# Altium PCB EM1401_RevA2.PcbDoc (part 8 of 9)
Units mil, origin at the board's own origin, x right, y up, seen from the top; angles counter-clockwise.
Board outline 7800 x 5300 mil, 6 copper layers (Top Layer, MidLayer1, MidLayer2, MidLayer3, MidLayer4, Bottom Layer), stack 16.8 mil thick; 751 components, 531 nets, 2554 pads, 1388 vias.
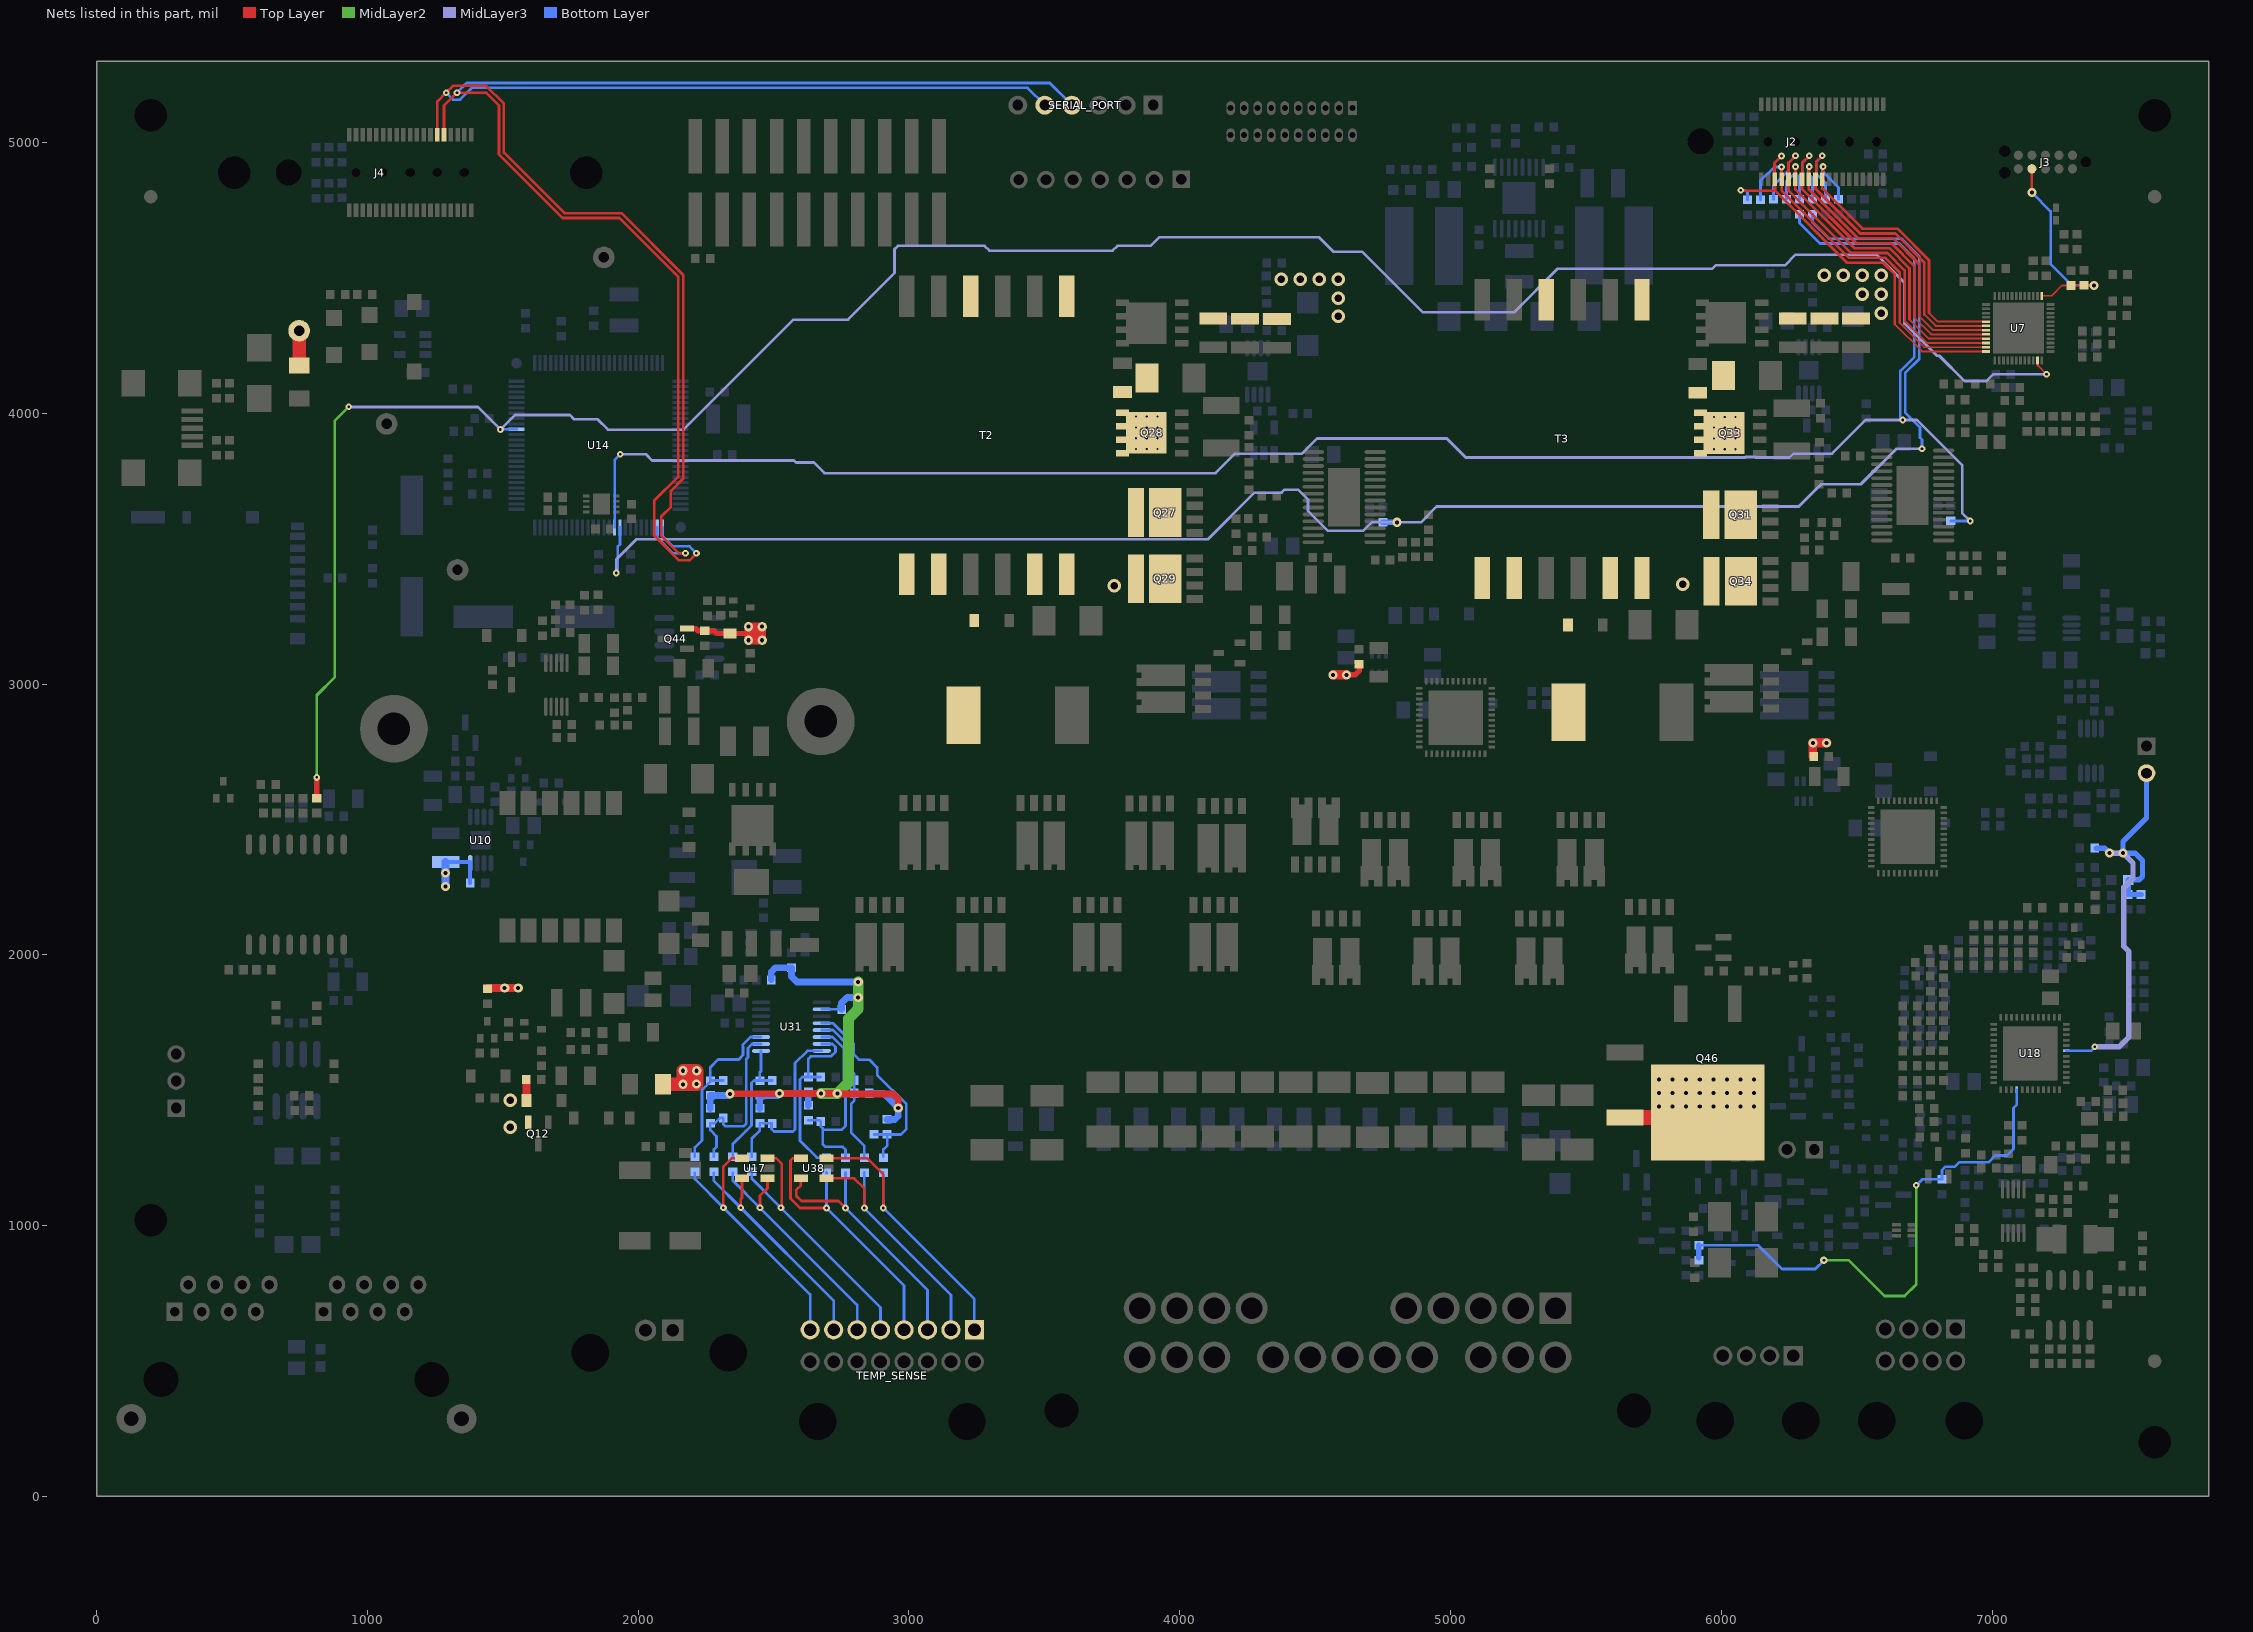
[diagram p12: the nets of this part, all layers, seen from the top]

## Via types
v1: diameter 25, hole 10, Top Layer to Bottom Layer, tented both sides, 275 vias
v2: diameter 16, hole 8, Top Layer to Bottom Layer, tented both sides, 240 vias
v3: diameter 34, hole 15, Top Layer to Bottom Layer, tented both sides, 158 vias
v4: diameter 34, hole 15, Top Layer to Bottom Layer, 154 vias
v5: diameter 34, hole 15, Top Layer to Bottom Layer, tented top, 95 vias
v6: diameter 34, hole 15, Top Layer to Bottom Layer, tented bottom, 89 vias
v7: diameter 25, hole 10, Top Layer to Bottom Layer, tented bottom, 75 vias
v8: diameter 25, hole 10, Top Layer to Bottom Layer, 62 vias
v9: diameter 28, hole 8, Top Layer to Bottom Layer, tented both sides, 60 vias
v10: diameter 24, hole 8, Top Layer to Bottom Layer, 53 vias
v11: diameter 25, hole 10, Top Layer to Bottom Layer, tented top, 28 vias
v12: diameter 50, hole 28, Top Layer to Bottom Layer, 28 vias
v13: diameter 25, hole 8, Top Layer to Bottom Layer, tented both sides, 18 vias
v14: diameter 50, hole 28, Top Layer to Bottom Layer, tented top, 12 vias
v15: diameter 25, hole 8, Top Layer to Bottom Layer, tented top, 9 vias
v16: diameter 20, hole 8, Top Layer to Bottom Layer, tented both sides, 9 vias
v17: diameter 24, hole 8, Top Layer to Bottom Layer, tented bottom, 4 vias
v18: diameter 24, hole 8, Top Layer to Bottom Layer, tented top, 4 vias
v19: diameter 28, hole 10, Top Layer to Bottom Layer, tented both sides, 3 vias
v20: diameter 35, hole 14, Top Layer to Bottom Layer, 3 vias
v21: diameter 50, hole 28, Top Layer to Bottom Layer, tented both sides, 2 vias
v22: diameter 50, hole 28, Top Layer to Bottom Layer, tented bottom, 2 vias
v23: diameter 30, hole 14, Top Layer to Bottom Layer, tented top, 2 vias
v24: diameter 28, hole 10, Top Layer to Bottom Layer, 1 vias
v25: diameter 35, hole 14, Top Layer to Bottom Layer, tented both sides, 1 vias
v26: diameter 35, hole 14, Top Layer to Bottom Layer, tented top, 1 vias

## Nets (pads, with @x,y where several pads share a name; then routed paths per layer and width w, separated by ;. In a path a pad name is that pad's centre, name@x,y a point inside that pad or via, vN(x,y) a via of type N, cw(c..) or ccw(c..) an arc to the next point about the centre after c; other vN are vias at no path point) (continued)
SP9: J2.19 R284.1 U7.41 | length 1149.5
  Top Layer w7: 6767,4371 6799.38,4338.62 U7.41@6977.91,4338.62
  Top Layer w10: v1(6376,4911) 6376,4867 J2.19@6373,4864 6373,4829.72 6520.72,4682 6650.35,4682 6767,4565.35 6767,4371
  Bottom Layer w10: v1@6373,4911 6373,4894 6433,4834 R284.1@6433,4791
SP10: J2.17 R282.1 U7.42 | length 1268.4
  Top Layer w7: 6749,4365 6791.13,4322.87 U7.42@6977.91,4322.87
  Top Layer w10: v1(6373,4951) 6350.5,4928.5 6350.5,4866.5 J2.17@6348,4864 6348,4829.27 6513.27,4664 6642.89,4664 6749,4557.89 6749,4365
  Bottom Layer w10: v1(6373,4951) 6350.5,4928.5 6350.5,4885.5 6385,4851 R282.1@6385,4791
SP11: J2.15 R281.1 U7.43 | length 1194.4
  Top Layer w7: 6731,4359 6782.87,4307.13 U7.43@6977.91,4307.13
  Top Layer w10: v1@6322,4911 v1@6323,4911 ; v1(6325,4911) 6325,4866 J2.15@6323,4864 6323,4828.81 6505.81,4646 6635.44,4646 6731,4550.44 6731,4359
  Bottom Layer w10: v1@6322,4911 6322,4883 6337,4868 R281.1@6337,4790
SP12: J2.13 R268.1 U7.44 | length 1324.4
  Top Layer w7: 6713,4353 6774.62,4291.38 U7.44@6977.91,4291.38
  Top Layer w10: J2.13@6298,4864 J2.13@6299,4865 ; v1(6325,4951) 6299.5,4925.5 6299.5,4865.5 J2.13@6299,4865 ; 6713,4353 6713,4542.98 6627.98,4628 6498.35,4628 6298,4828.35 6298.97,4863.97 J2.13@6299,4865
  Bottom Layer w10: R268.1@6289,4790 6289,4877 6299.5,4887.5 6299.5,4925.5 v1(6325,4951)
SP13: J2.11 R267.1 U7.45 | length 1264.3
  Top Layer w7: 6695,4347 6766.37,4275.63 U7.45@6977.91,4275.63
  Top Layer w10: v1@6271,4911 v1@6273,4911 ; v1(6274,4911) 6274,4865 J2.11@6273,4864 6273,4827.9 6490.9,4610 6620.52,4610 6695,4535.52 6695,4347
  Bottom Layer w10: R267.1@6241,4790 6241,4857 6274,4890 v1(6274,4911)
SP14: J2.9 R258.1 U7.46 | length 1406.1
  Top Layer w7: 6677,4341 6758.12,4259.88 U7.46@6977.91,4259.88
  Top Layer w10: v1(6274,4951) 6248,4925 J2.9@6248,4864 6248,4823 6479,4592 6613.07,4592 6677,4528.07 6677,4341
  Bottom Layer w10: R258.1@6193,4790 6193,4841 6248,4896 6248,4925 v1(6274,4951)
SP15: J2.7 R254.1 U7.47 | length 1359.2
  Top Layer w7: 6659,4335 6749.87,4244.13 U7.47@6977.91,4244.13
  Top Layer w10: v1(6222,4910) 6222,4865 J2.7@6223,4864 6223,4822.54 6471.54,4574 6605.61,4574 6659,4520.61 6659,4335
  Bottom Layer w10: R254.1@6145,4789 6145,4859 6196,4910 v1(6222,4910)
SP16: J2.5 R253.1 U7.48 | length 1454.3
  Top Layer w7: 6641,4329 6741.61,4228.39 U7.48@6977.91,4228.39
  Top Layer w10: v1(6072,4824) 6073.91,4822.09 6198,4822.09 ; v1(6222,4950) 6196.5,4924.5 6196.5,4865.5 J2.5@6198,4864 6198,4822.09 ; 6641,4329 6641,4513.16 6598.16,4556 6464.09,4556 6198,4822.09
  Bottom Layer w10: v1(6072,4824) 6088,4824 6097,4815 R253.1@6097,4789
SUPPLY: C67.1 D45.1 F17.1 Q44.2 R93.1 R145.2 U10.8 | length 1020.8
  Top Layer w20: Q44.2@2180.09,3205.4 2212.6,3205.4 2220.44,3197.56 R145.2@2246,3197.56 2279.44,3197.56 2290,3187 D45.1@2339,3187 2408,3187 2457,3187 2458,3186
  Top Layer w30: v3(2408,3162) 2408,3187 v3(2408,3212) v3(2458,3212) 2458,3186 v3(2458,3162) v3(2408,3162)
  Top Layer w50: F17.1@2091.02,1522 v4(2166,1522) ; v4(2166,1522) 2216,1522 v6(2215,1523) 2216,1524 v6(2216,1572) v4(2166,1572) v4(2166,1522)
  Bottom Layer w15: C67.1@1289,2343 1289.34,2343.34 1379.61,2343.34 U10.8@1379.61,2338.37 R93.1@1379.61,2266
  Bottom Layer w30: v6(1289,2252) v6(1289,2302) C67.1@1289,2343
SYNC_: R165.1 U7.11 U14.66 | length 8827.2
  Top Layer w7: U7.11@7167.87,4195.91 7167.87,4177.13 v1(7201,4144)
  Top Layer w20: R165.1@813,2579.12 v1(813,2655.56)
  MidLayer2 w10: v1(813,2655.56) 813,2958.8 880,3025.8 880,3973 v7(931,4024)
  MidLayer3 w10: v7(931,4024) 932,4023 1408.11,4023 v7(1491.11,3940) 1544.99,3993.88 1747.69,3993.88 1763.56,3978 1850,3978 1888.5,3939.5 2167.5,3939.5 2574,4346 2775.09,4346 2947,4517.91 2947,4606 2959.62,4618.62 3279.12,4618.62 3297.12,4600.62 3751.62,4600.62 3769.62,4618.62 3892.62,4618.62 3924.62,4650.62 4513.3,4650.62 4566.91,4597 4673.91,4597 4897.3,4373.62 5235.62,4373.62 5396,4534 5966.86,4534 5979.24,4546.38 6234.76,4546.38 6274.38,4586 6572.54,4586 6675.73,4482.82 6675.73,4332 6676.37,4332 6795.87,4212.5 6804.93,4212.5 6898.43,4119 6979,4119 7004,4144 v1(7201,4144)
  Bottom Layer w10: v7(1491.11,3940) 1490.06,3941.06 U14.66@1550.85,3941.06
TIN_M_BOT: C125.1 D62.1 Q28.5 Q28.6 Q28.7 Q28.8 Q28.9 T2.1
  other v9: 3838.5,3868 3878.5,3868 3918.5,3868 3838.5,3908 3878.5,3908 3918.5,3908 3838.5,3948 3878.5,3948 3918.5,3948 3838.5,3988 3878.5,3988 3918.5,3988
TIN_M_TOP: C135.1 D63.1 Q33.5 Q33.6 Q33.7 Q33.8 Q33.9 T3.1
  other v9: 5972.5,3867 6012.5,3867 6052.5,3867 5972.5,3907 6012.5,3907 6052.5,3907 5972.5,3947 6012.5,3947 6052.5,3947 5972.5,3987 6012.5,3987 6052.5,3987
TIN_P_BOT: C122.1 C123.1 C124.1 C132.1 C133.1 C134.1 D10.1 Q12.2 Q46.4 R23.2 R29.2 R37.2 R166.1 R210.2 T2.4 T3.4 | length 732.5
  Top Layer w20: v3(4616.42,3034) 4648,3034 4662.42,3048.42 R23.2@4662.42,3073.94
  Top Layer w30: R210.2@1443,1877.99 v3(1506.99,1877.99) v3(1556.99,1877.99) ; R37.2@1587.44,1540 1587.44,1463.56 D10.1@1588,1463 ; R29.2@6337.92,2733 6337.92,2782.35 v4(6338.57,2783)
  Top Layer w35: v3(4566.42,3034) v3(4616.42,3034) ; v4(6338.57,2783) v4(6388.57,2783)
  Top Layer w55: R166.1@5644.42,1400 5932.42,1400 Q46.4@5950.42,1418
  other v6: 5770.42,1440 5820.42,1440 5870.42,1440 5920.42,1440 5970.42,1440 6020.42,1440 6070.42,1440 6120.42,1440 5770.42,1490 5820.42,1490 5870.42,1490 5920.42,1490 5970.42,1490 6020.42,1490 6070.42,1490 6120.42,1490 5770.42,1540 5820.42,1540 5870.42,1540 5920.42,1540 5970.42,1540 6020.42,1540 6070.42,1540 6120.42,1540
  other v12: 1528,1363 1527.44,1463.56 4585.42,4359 4585,4425 4375,4495 4445,4495 4515,4495 4585,4495
  other v14: 6590.42,4370 6520.42,4440 6590.42,4440 6380.42,4510 6450.42,4510 6520.42,4510 6590.42,4510
TOP_MOD_ID: R55.2 R113.1 R184.1 U18.45 | length 1995.4
  MidLayer2 w10: v19(6379,872) 6471,872 6603,740 6677,740 6720,783 v1(6720,1149)
  Bottom Layer w10: R184.1@5917,927.44 6136.56,927.44 6224,840 6347,840 v19(6379,872) ; v1(6720,1149) 6742.12,1171.12 R113.1@6815.42,1171.12 6815.42,1205.87 6827.55,1218 6862.34,1218 6878.34,1234 6986.1,1234 7010.84,1258.75 7054.75,1258.75 7078.92,1282.92 7078.92,1434.68 7091.48,1447.24 U18.45@7091.48,1502.07
  Bottom Layer w20: R55.2@5917,882.12 R184.1@5917,927.44
TOUT_M_BOT: Q29.5 Q29.6 T2.11 T2.12
  other v12: 3757.42,3363
TOUT_M_TOP: Q34.5 Q34.6 T3.11 T3.12
  other v12: 5858.42,3368
TOUT_P_BOT: Dclamp1.2 L5.1 Q27.5 Q27.6 T2.7 T2.8
TOUT_P_TOP: Dclamp2.2 L7.1 Q31.5 Q31.6 T3.7 T3.8
TS0: C141.1 R68.1 R201.1 U31.4 | length 781.4
  Bottom Layer w10: U31.4@2678.12,1747.8 2718.62,1747.8 2796.42,1670 2796.42,1632 2815.42,1613 2853.42,1613 2882.42,1584 2882.42,1557 2990.42,1449 2990.42,1357 ; C141.1@2871.42,1337 R201.1@2919.42,1337 ; R68.1@2905.42,1255 2905.42,1281 2919.42,1295 R201.1@2919.42,1337 ; 2990.57,1357.16 2990.42,1357 ; R201.1@2919.42,1337 2970.42,1337 2990.42,1357
TS1: C142.1 R69.1 R202.1 U31.5 | length 566.1
  Bottom Layer w10: U31.5@2678.12,1722.21 2718.75,1722.21 2778.42,1662.54 2778.42,1580 2798.42,1560 C142.1@2798.42,1537 2798.42,1462 2786.42,1450 2786.42,1343.31 2835.42,1294.31 R69.1@2835.42,1255
TS2: C143.1 R70.1 R203.1 U31.6 | length 732
  Bottom Layer w10: R203.1@2628.42,1388.88 2628.53,1389 2669.42,1389 C143.1@2674.42,1384 2674.42,1366 2681.15,1359.27 ; U31.6@2678.12,1696.62 2717.8,1696.62 2760.42,1654 2760.42,1505.43 2765.42,1500.43 2765.42,1368 2751.42,1354 2686.42,1354 2681.15,1359.27 ; R70.1@2765.42,1255 2765.42,1281 2755.42,1291 2692.42,1291 2681.15,1302.27 2681.15,1359.27
TS3: C146.1 R71.1 R204.1 U31.7 | length 682
  Bottom Layer w10: C146.1@2673.42,1549 R204.1@2628.42,1549 ; U31.7@2678.12,1671.02 2717.94,1671.02 2728.95,1660.01 2728.95,1641.56 2712.93,1625.54 2637.96,1625.54 2628.42,1616 R204.1@2628.42,1549 ; R71.1@2695.42,1251.06 2659.87,1251.06 2597.42,1313.52 2597.42,1540 2606.42,1549 R204.1@2628.42,1549
TS4: C147.1 R72.1 R205.1 U31.8 | length 678
  Bottom Layer w10: R72.1@2419.42,1254 2419.42,1322 2449.42,1352 R205.1@2449.42,1377.88 2449.53,1378 2492.42,1378 2492.42,1358 2502.42,1348 2571.4,1348 2579.28,1355.88 2579.28,1377.57 ; 2579.28,1400.12 2579.28,1377.57 ; U31.8@2678.12,1645.43 2624.85,1645.43 2579.42,1600 2579.42,1377.57 2579.28,1377.57
TS5: C148.1 R73.1 R206.1 U31.9 | length 493.6
  Bottom Layer w10: R73.1@2349.42,1254 2349.42,1302 2397.68,1350.27 2398,1350.27 2418.42,1370.68 2418.42,1527 2427.42,1536 R206.1@2449.42,1536 ; U31.9@2453.71,1645.43 2453.71,1570.3 2449.42,1566 R206.1@2449.42,1536 ; C148.1@2495.3,1536 R206.1@2449.42,1536
TS6: C150.1 R74.1 R207.1 U31.10 | length 645.4
  Bottom Layer w10: R74.1@2279.42,1254 2279.42,1281 2289.57,1291.16 2289.57,1329.84 2266.42,1353 R207.1@2266.42,1378 2281.42,1378 2301.42,1398 C150.1@2314.3,1398 2314.3,1375.12 2322.42,1367 2388.96,1367 2390.23,1368.27 2390.55,1368.27 2399.42,1377.13 2399.42,1616 2405.3,1621.88 2405.3,1655.88 2420.44,1671.02 U31.10@2453.71,1671.02
TS7: C151.1 R75.1 R208.1 U31.11 | length 659.8
  Bottom Layer w10: R75.1@2209.42,1254 2209.42,1289 2235.42,1315 2235.42,1500.75 2266.42,1531.75 R208.1@2266.42,1536 ; C151.1@2314.42,1536 R208.1@2266.42,1536 ; U31.11@2453.71,1696.62 2415.58,1696.62 2385.94,1666.98 2385.94,1661.98 2387.3,1660.61 2387.3,1629.88 2371.42,1614 2295.42,1614 2266.42,1585 R208.1@2266.42,1536
TS_0: R68.2 TEMP_SENSE.1 U38.3 | length 1077.9
  Top Layer w10: U38.3@2695.42,1249.4 2844.6,1249.4 2905.42,1188.58 v1(2905.42,1065.58)
  Bottom Layer w10: R68.2@2905.42,1195.94 v1(2905.42,1065.58) 3241.68,729.32 TEMP_SENSE.1@3241.68,615.48
TS_1: R69.2 TEMP_SENSE.2 U38.1 | length 939.6
  Top Layer w10: U38.1@2695.42,1174.6 2797.4,1174.6 2835.42,1136.58 v1(2835.42,1065.58)
  Bottom Layer w10: R69.2@2835.42,1195.94 v1(2835.42,1065.58) 2835.42,1063.58 3155.07,743.93 TEMP_SENSE.2@3155.07,615.48
TS_2: R70.2 TEMP_SENSE.3 U38.5 | length 977.9
  Top Layer w10: U38.5@2600.93,1174.6 2600.93,1148.99 2583.5,1131.56 2583.5,1110.44 2602.85,1091.08 2739.92,1091.08 v1(2765.42,1065.58)
  Bottom Layer w10: R70.2@2765.42,1195.94 v1(2765.42,1065.58) 3068.46,762.54 TEMP_SENSE.3@3068.46,615.48
TS_3: R71.2 TEMP_SENSE.4 U38.4 | length 1035.7
  Top Layer w10: U38.4@2600.93,1249.4 2571.82,1249.4 2562.34,1239.92 2562.34,1100.66 2597.42,1065.58 v1(2695.42,1065.58)
  Bottom Layer w10: v1@2695.42,1058.42 v1(2695.42,1065.58) ; R71.2@2695.42,1195.94 v1(2695.42,1065.58) ; TEMP_SENSE.4@2981.84,615.48 2981.84,779.16 v1(2695.42,1065.58)
TS_4: R72.2 TEMP_SENSE.5 U17.3 | length 1002.3
  Top Layer w10: U17.3@2477.66,1249.4 2509.6,1249.4 2530,1229 v1@2530,1064
  Bottom Layer w10: R72.2@2419.42,1194.94 2419.42,1173.58 v1(2527,1066) 2895.23,697.77 TEMP_SENSE.5@2895.23,615.48
TS_5: R73.2 TEMP_SENSE.6 U17.1 | length 889.7
  Top Layer w10: v1(2450,1066) 2450,1110.58 2477.66,1138.24 U17.1@2477.66,1174.6
  Bottom Layer w10: R73.2@2349.42,1194.94 2349.42,1166.58 v1(2450,1066) 2808.61,707.39 TEMP_SENSE.6@2808.61,615.48
TS_6: R74.2 TEMP_SENSE.7 U17.5 | length 876
  Top Layer w10: v1(2378.84,1066.17) 2379,1066.33 2379,1099 2383.17,1103.17 U17.5@2383.17,1174.6 U17.5@2380.19,1174.6
  Bottom Layer w10: R74.2@2279.42,1194.94 2279.42,1165.59 v1(2378.84,1066.17) 2722,723.01 TEMP_SENSE.7@2722,615.48
TS_7: R75.2 TEMP_SENSE.8 U17.4 | length 988.9
  Top Layer w10: v1(2314.76,1066.24) 2314.76,1217.76 2346.4,1249.4 U17.4@2383.17,1249.4
  Bottom Layer w10: R75.2@2209.42,1194.94 2209.42,1171.58 v1(2314.76,1066.24) 2635.39,745.61 TEMP_SENSE.8@2635.39,615.48
UART_RX: J4.30 SERIAL_PORT.4 U14.26 | length 5079.5
  Top Layer w10: J4.30@1283,5028 1283,5136 v8(1331,5184) 1438,5184 1486,5136 1486,4955.46 1720.46,4721 1930.28,4721 2148.5,4502.78 2148.5,3767.04 2059.5,3678.04 2059.5,3549.04 2151.54,3457 2189,3457 v1(2215,3483)
  Bottom Layer w10: v8(1331,5184) 1367,5220 3520,5220 SERIAL_PORT.4@3602,5138 ; U14.26@2090.22,3578.85 2090.22,3546.78 2128.44,3508.56 2189.44,3508.56 v1(2215,3483)
UART_TX: J4.28 SERIAL_PORT.5 U14.27 | length 4996.6
  Top Layer w10: J4.28@1257.5,5028.5 J4.28@1258,5028 1258.5,5028.5 1258.5,5151.5 v8(1291,5184) 1316.5,5209.5 1437.96,5209.5 1504,5143.46 1504,4962.91 1727.91,4739 1937.73,4739 2166.5,4510.23 2166.5,3759.59 2120.5,3713.59 2120.5,3653.5 2085,3618 2085,3549 2151,3483 v1(2175,3483)
  Bottom Layer w10: v8(1291,5184) 1316.5,5158.5 1342.04,5158.5 1385.54,5202 3438,5202 SERIAL_PORT.5@3502,5138 ; U14.27@2070.54,3578.85 2070.54,3541.01 2128.54,3483 v1(2175,3483)
USB_VBUS: F16.2 TP5.1 | length 128
  Top Layer w50: F16.2@748,4177 TP5.1@748,4305
VPUMP: C224.2 C227.2 J3.7 U7.25 | length 780.8
  Top Layer w7: U7.25@7183.61,4434 7220,4434 7258,4472 C224.2@7292,4472 C227.2@7334.56,4472 ; C227.2@7335,4472.44 C227.2@7334.56,4472 ; C227.2@7339.56,4472 C227.2@7334.56,4472
  Top Layer w10: v3(7147,4815) J3.7@7147,4903 ; C227.2@7340,4472.44 v3(7376,4472.44)
  Bottom Layer w10: v3(7147,4815) 7216.5,4745.5 7216.5,4551.5 7295.27,4472.73 7375.71,4472.73 v3(7376,4472.44)
VREF: C149.1 R105.2 R201.2 R202.2 R203.2 R204.2 R205.2 R206.2 R207.2 R208.2 R240.1 U31.2 | length 2401.8
  Top Layer w25: v4(2339.42,1487) 2522.42,1487 2523.42,1488 v4(2675.42,1488) v4(2735.42,1488) ; v4@2735.42,1486.5 2941.92,1486.5 2960.42,1468 v3(2960.42,1435)
  MidLayer2 w40: v4(2675.42,1488) v4(2735.42,1488) 2776.42,1529 2776.42,1764 2812.53,1800.12 v3(2812.53,1843) v3(2812.53,1900)
  Bottom Layer w10: U31.2@2678.12,1798.98 C149.1@2751.42,1799
  Bottom Layer w20: R105.2@2491.53,1908 R105.2@2491.65,1907.88 ; v3@2810.53,1902 v3(2812.53,1900)
  Bottom Layer w25: R207.2@2266.42,1433.12 R208.2@2266.42,1480.88 2333.3,1480.88 v4(2339.42,1487) ; R205.2@2449.42,1433 R206.2@2449.42,1480.88 2515.3,1480.88 v4(2522.42,1488) ; R105.2@2491.53,1908 2491.53,1936.53 2507.88,1952.88 R240.1@2566,1952.88 2566,1920 2586,1900 v3@2811.53,1900 ; R203.2@2628.42,1444 2628.42,1488 v4(2675.42,1488) v4(2735.42,1488) ; C149.1@2751.42,1799 2751.42,1822.42 2772,1843 v3@2811.53,1843 ; v3@2810.53,1841 v3(2812.53,1843) ; v3(2812.53,1900) v3@2811.53,1900 ; v3@2816.33,1843 2814.43,1841.1 v3(2812.53,1843) ; R202.2@2853.53,1489 2906.42,1489 v3(2960.42,1435) 2960.42,1405 2947.53,1392.12 R201.2@2919.42,1392.12 ; v3@2811.53,1843 v3@2811.53,1900 ; v3@2811.53,1843 v3(2812.53,1843)
VREF_BOT_: R54.2 R281.2 U14.34 | length 6651.8
  MidLayer3 w10: v1(1919,3410) 1919,3460 1994,3535 4104,3535 4276,3707 4375.75,3707 4386.75,3718 4436.42,3718 4473.42,3681 4473.42,3639.62 4547.03,3566 4677.42,3566 4708.74,3597.32 v5(4802.74,3597.32) 4890.32,3597.32 4949,3656 6286,3656 6368,3738 6515,3738 6646,3869 v8(6741,3869)
  Bottom Layer w10: v1(1919,3410) 1924.27,3415.27 1924.27,3507.44 1932.74,3515.91 U14.34@1932.74,3578.85 ; R281.2@6337,4734.88 6337,4705 6397,4645 6665.18,4645 6731,4579.18 6731,4200.54 6679,4148.54 6679,4003 6734,3948 6734,3910.09 6741,3903.09 v8(6741,3869)
  Bottom Layer w20: R54.2@4750.42,3597.32 v5(4802.74,3597.32)
VREF_OUT: R133.2 R136.2 R140.2 RT1.1 RT2.2 U18.30 | length 1756.2
  MidLayer3 w20: v1(7379.41,1660.65) 7469.07,1660.65 7505.42,1697 7505.42,2012.5 7486.42,2031.5 7486.42,2249 7520.42,2283 7520.42,2339 v5(7483.42,2376) v3(7433.42,2376)
  Bottom Layer w10: U18.30@7274.55,1645.77 7364.52,1645.77 v1(7379.41,1660.65)
  Bottom Layer w20: R140.2@7383.98,2394 7415.42,2394 v3(7433.42,2376) v5(7483.42,2376) ; RT1.1@7502.53,2275 7502.42,2274.89 R136.2@7502.42,2223 R133.2@7550.42,2223 ; RT1.1@7502.53,2277 7542.42,2277 7555.42,2290 7555.42,2348 7527.42,2376 v5(7483.42,2376) ; RT2.2@7570.42,2671 7570.42,2505.42 7483.42,2418.42 v5(7483.42,2376)
VREF_TOP_: R53.2 R268.2 U14.35 | length 6896.2
  MidLayer3 w10: v1(1934,3849) 2027.94,3849 2051.44,3825.5 2575.53,3825.5 2583.03,3818 2649.09,3818 2688.09,3779 4132.53,3779 4204.53,3851 4450.84,3851 4506.84,3907 4986.21,3907 5056.21,3837 6088.48,3837 6089.98,3838.5 6126.02,3838.5 6127.52,3837 6251.91,3837 6265.91,3851 6409.27,3851 6533.27,3975 v1(6670,3975) 6723,3975 6889.42,3808.58 6889.42,3632 v11(6919.42,3602)
  Bottom Layer w10: U14.35@1913.06,3578.85 1913.06,3828.06 v1(1934,3849) ; R268.2@6289,4734.88 6289,4703 6365,4627 6657.72,4627 6713,4571.72 6713,4208 6661,4156 6661,3984 v1(6670,3975) ; R53.2@6847.42,3602.88 6848.3,3602 v11(6919.42,3602)
pads on no net: BATTERY.0 BATTERY.12 BATTERY.13 BATTERY.18 D2.1 D5.2 D7.1 D16.2 D19.2 J2.0 J2.6 J2.8 J2.10 J2.12 J2.14 J2.16 J2.18 J2.20 J2.22 J2.24 J2.26 J2.28 J2.30 J2.32 J2.34 J2.36 J2.38 J3.0 J3.4 J4.0 J4.37 J4.38 J5.0 J5.1 J5.2 J5.8 MNT1.1 MNT2.1 MNT3.1 MNT4.1 MNT5.1 MNT6.1 MNT7.1 MNT8.1 P1.4 P2.0 P3.0 P3.A6 P3.B6 PING_IN1.0 PING_OUT1.0 PING_OUT1.2 PING_OUT1.8 SERIAL_PORT.2 SERIAL_PORT.3 SERIAL_PORT.6 T2.5 T2.6 T3.5 T3.6 TEMP_SENSE.0 TEST_PORT.6 TEST_PORT.15 TEST_PORT.18 U1.1 U2.2 U2.6 U2.7 U2.27 U2.29 U2.30 U2.34 U2.45 U4.2 U4.6 U4.8 U4.10 U4.11 U4.15 U10.3 U10.6 U10.7 U12.5 U12.8 U14.101 U14.102 U19.1 U20.2 U20.6 U20.8 U20.10 U20.11 U20.15 U24.1 U27.26 U28.1 U29.26 U30.5 U30.8 U46.1
copper on no net: | length 345.6
  Top Layer w10: 62,2929 ccw(c117,2929) 172,2929 ccw(c117,2929) 62,2929

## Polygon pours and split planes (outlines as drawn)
+5V_CAN on MidLayer2 "Top Layer-5V_CAN" (solid, pour order 71): 210,210 210,2055 930,2055 1035,1950 1035,1195 1085,1145 1395,835 1395,810 1395,210
+12V on MidLayer2 "MidLayer2-+12V" (solid, pour order 79): 3065,5140 5190,5140 5190,4530 5135,4530 5135,4582 5048,4582 5048,4174 4555,4175 4555,4210 4350,4210 4350,3630 3655,3630 3655,835 1920,835 1920,1720 2295,1720 2295,1235 3065,1235
+3V3 on MidLayer1 "MidLayer1-3v3" (solid, pour order 65): 7580,2415 6885,2415 6885,2525 6970,2525 6970,3990 6655,3990 6655,4551 5430,4551 5430,4415 5095,4415 5095,3285 5250,3285 5250,2660 4960,2660 4960,4550 1105,4551 1105,4390 1300,4390 1300,3005 1645,3005 1645,2950 2375,2950 2375,1865 2190,1865 2190,1980 1330,1980 1330,2390 680,2390 680,5250 5340,5250 5340,4925 5979.71,4925 5980,5040 7070,5040 7070,4775 7280,4775 7280,4515 7580,4515
+5V5 on MidLayer1 "MidLayer4-5V5" (solid, pour order 75): 5375,5260 5375,4925 5980,4925 5980,5055 7085,5055 7085,4790 7295,4790 7295,4525 7605,4525 7605,3785 7545,3785 7545,3005 7740,3005 7740,4975 7470,4975 7470,5260
BAT0 on MidLayer1 "MidLayer1-BAT0" (solid, pour order 122): 5550,727 5355,727 5355,660 5475,660 5475,580 5537,580 5537,663 5550,663
AGND on MidLayer1 "MidLayer4-AGND" (solid, remove dead copper, pour order 74): 5654,285 7234.42,285 7635,685.58 7635,1525 7610.42,1525 7610.42,1752 7533.42,1752 7533.42,2140 7325.42,2140 7325.42,1750 7025.42,1750 7025.42,1430 6792.42,1430 6763.42,1459 6640.42,1459 6640.42,1345 6715.42,1345 6805.42,1255 7220.42,1255 7220.42,1055 6905.42,1055 6905.42,990 6990.42,990 6991.52,770 5654,770
+3V3_LP on MidLayer1 "MidLayer1-3V3_LP" (solid, pour order 67): 1325,3015 1325,4420 1125,4420 1125,4555 1365,4556 2428,4556 2428,2965 1655,2965 1655,3080 1580,3080 1580,3015
TIN_P_BOT on MidLayer1 "MidLayer1-INPUT" (solid, remove dead copper, pour order 77): 6635,4555 6635,3975 6950,3975 6950,2550 6870,2550 6870,1780 6414.27,1324.27 1345,1325.03 1345,1959.93 4145,1960.5 4145,4110 4330,4110 4330,4555 4954.4,4555 4955.08,2675.2 5275,2674.86 5275,3295 6330,3295 6330,3975 6365,3975 6365,4555
CAN_GND on MidLayer1 "MidLayer1-GND_CAN" (solid, pour order 70): 210,2055 935,2055 935,2050 1035,1950 1035,1195 1395,835 1395,210 210,210
NetQ14_5 on MidLayer1 "MidLayer1-Q15" (solid, pour order 69): 4485,1765 5970,1765 6265,2060 6265,2725 6320,2725 6320,2975 5660,2975 5660,2184.73 4485,2184.01
NetQ1_5 on MidLayer1 "MidLayer4-Q1_top" (solid, pour order 72): 2965.42,2345 4145,2345 4145,2845 4260,2845 4260.42,2955 2964.92,2955
NetQ2_3 on MidLayer1 "MidLayer1-Q2_top" (solid, remove dead copper, pour order 76): 4130,3284 2440,3284 2440,1865 4145,1865 4145,2330 2945,2330 2945,2955 4259.64,2955 4260,3085 4130,3085
NetQ15_3 on MidLayer1 "MidLayer4-Q15_bot" (solid, pour order 73): 4485,2215 4485,2658 5265,2658 5265,3284 6315,3284 6315,2961 5634.71,2961 5634.71,2215
BAT0 on MidLayer1 "MidLayer1-GND" (solid, pour order 64): 5440,4540 5440,4405 5105,4405 5105,3295 6320,3295 6320,3985 6355,3985 6355,4540
BAT0 on MidLayer1 "MidLayer1-GND" (solid, pour order 63): 2440,3299 2440,4535 4320,4535 4320,4120 4135,4120 4135,3300
+5V5 on Bottom Layer "Bottom Layer-5V5" (solid, pour order 80): 5640,4475 5640,4795 5590,4795 5590,5060 5750,5060 5750,4475
BAT0 on Bottom Layer "Bottom Layer-GND_tie" (solid, pour order 81): 2790.42,1820 2790.42,1695 2810.42,1675 2810.42,1640 2825.42,1625 2940.42,1625 2940.42,1710 3080.42,1710 3080.42,1935 2840.42,1935 2845.42,1930 2845.42,1820
BAT0 on MidLayer4 "MidLayer4-GND" (solid, pour order 62): 50,5250 7750,5250 7750,35 1745,35 1745,950 1360,1335 1360,2090 1085,2365 1080,2370 50,2370
CAN_GND on MidLayer4 "MidLayer1-GND_CAN" (solid, pour order 68): 210,2055 935,2055 935,2050 1035,1950 1035,1195 1395,835 1395,210 210,210
SUPPLY on MidLayer3 "MidLayer3-Supply" (solid, pour order 66): 2245,1480 2245,1865 2100,1865 1935,2030 1935,2660 1720,2660 1720,3125 2490,3125 2490,3395 1250,3395 1250,2235 1385,2100 1390,2095 1390,1480
+12VF1 on MidLayer3 "MidLayer3-+12VF1" (solid, pour order 78): 2730.42,2062 2730.42,1978.43 2680.42,1945 2575.42,1945 2575.42,2062
NetC136_1 on Top Layer "Top Layer-Plus Top" (solid, pour order 118): 5759.42,2790 6119.42,2790 6119.42,3140 6225.42,3140 6225.42,3106 6260.42,3106 6260.42,3140 6394.42,3140 6394.42,3315 6229.42,3315 6229.42,3275 5826.42,3275 5826.42,3005 5759.42,3005
GNDF2 on Top Layer "Top Layer-GNDF2" (solid, pour order 119): 6429.42,2910 6429.42,3065 6298,3065 6298,3095 6444.42,3095 6444.42,3465 6579.42,3465 6579.42,3485 6660.42,3485 6660.42,3375 6700.42,3375 6700.42,3330 6534.42,3330 6534.42,2910
BAT0 on Top Layer "Top Layer-GND" (solid, pour order 86): 6120.42,4371 6120.42,4090 6195.42,4090 6195.42,4005 6335.42,4005 6335.42,4020 6385.42,4020 6385.42,4220 6550.42,4220 6550.42,4270 6190.42,4270 6190.42,4371
NetC235_2 on Top Layer "Top Layer-NetC235" (solid, pour order 85): 6117,3965 6117,3834 6326.42,3834 6326.42,3911.39 6175,3911.39 6175,3965
BAT0 on Top Layer "Top Layer-GND" (solid, pour order 87): 3980.42,4370 3980.42,4085 4080.42,4085 4080.42,4000 4225.42,4000 4225.42,3955 4275.42,3955 4275.42,4115 4343.42,4115 4343.42,4214 4435.42,4214 4435.42,4265 4045.42,4265 4045.42,4370
NetC233_1 on Top Layer "Top Layer-NetC233_1" (solid, pour order 114): 4225.42,3840 3980.42,3840 3980.42,3967 4045.42,3967 4045.42,3907 4225.42,3907
BAT0 on Top Layer "Top Layer-GND" (solid, pour order 84): 2165.42,2734 2164.99,2997 2149,2997 2149,3023 2130,3023 2130,3096 2186,3096 2186,3015.01 2362,3014.99 2362,2734
NetD5_3 on Top Layer "Top Layer-Fuse1" (solid, remove dead copper, pour order 110): 5840.42,1750 5531.42,1441 5404.42,1441 5404.42,1521 5744,1861.5 5744,2104 5970,2104 5970,1750
NetF6_2 on Top Layer "Top Layer-Fuse6" (solid, pour order 102): 4776.42,1485 4649.42,1485 4649.42,1770 4702,1822.58 4702,2185 4769,2252 4769,2332 4841,2332 4841,1790.58 4776.42,1726
NetF8_2 on Top Layer "Top Layer-NFuse8" (solid, pour order 100): 4165,2483 4436,2483 4436,2411 4394,2411 4394,1932 4493.42,1832.58 4493.42,1485 4366.42,1485 4366.42,1806.58 4265.42,1907.58 4265.42,2285 4245.42,2305 4165,2305
NetF2_1 on Top Layer "Top Layer-Fuse2" (solid, pour order 109): 5388.42,1440 5261.42,1440 5261.42,1598.42 5452,1789 5452,2204 5492,2244 5492,2310 5570,2310 5570,1716 5388.42,1534.42
NetF3_1 on Top Layer "Top Layer-Fuse3" (solid, pour order 108): 5201.42,1485 5075.42,1485 5075.42,1619.42 5339,1883 5339,2019 5418,2019 5418,1792.58 5201.42,1576
NetF4_1 on Top Layer "Top Layer-Fuse4" (solid, pour order 105): 5073,2211 5109,2247 5109,2305 5187,2304 5187,1774 5059.42,1646.42 5059.42,1485 4933.42,1485 4933,1683 5073,1822
NetF5_1 on Top Layer "Top Layer-Fuse5" (solid, pour order 107): 4917.42,1485 4791.42,1485 4791.42,1716 4959,1883.58 4959,1950 5037,1950 5037,1808.58 4917.42,1689
NetF7_1 on Top Layer "Top Layer-Fuse7" (solid, pour order 90): 4633.42,1485 4507.42,1485 4507.42,1785 4588,1865.58 4588,1987 4668,1987 4668,1807.58 4633.42,1773
NetF15_1 on Top Layer "Top Layer-Fuse15" (solid, pour order 115): 2903,2117 2982,2117 2982,1886 3351.42,1516.58 3351.42,1439 3225.42,1439 3225.42,1455 2903,1777.42
NetF14_1 on Top Layer "Top Layer-Fuse14" (solid, pour order 113): 3060.42,2495 3150.42,2495 3150.42,1934.58 3576.42,1508.58 3576.42,1439 3446.42,1439 3446.42,1452.58 3043,1856 3043,2287.58 3060.42,2305
NetF9_1 on Top Layer "Top Layer-Fuse9" (solid, pour order 111): 4130.42,2120 4130.42,1849.58 4221.42,1758.58 4221.42,1485 4349.42,1485 4349.42,1788.58 4220.42,1917.58 4220.42,2120
NetF10_1 on Top Layer "Top Layer-Fuse10" (solid, pour order 93): 3895.42,2495 3895.42,2305 3880.42,2290 3880.42,1875.58 4081.42,1674.58 4081.42,1485 4206.42,1485 4206.42,1730.58 4000.42,1936.58 4000.42,2175 3985.42,2190 3985.42,2495
NetF11_1 on Top Layer "Top Layer-Fuse11" (solid, pour order 96): 3700.42,2120 3790.42,2120 3790.42,1925.58 4064.42,1651.58 4064.42,1485 3938.42,1485 3938.42,1618.58 3700.42,1856.58
NetF12_1 on Top Layer "Top Layer-Fuse12" (solid, pour order 99): 3490.42,2495 3580.42,2495 3580.42,1933.58 3923.42,1590.58 3923.42,1485 3796.42,1485 3796.42,1560.58 3450.42,1906.58 3450.42,2270 3490.42,2310
NetF13_1 on Top Layer "Top Layer-Fuse13" (solid, pour order 112): 3270.42,2120 3360.42,2120 3360.42,1963.58 3780.42,1543.58 3780.42,1490 3655.42,1490 3270.42,1875
TIN_M_TOP on Top Layer "Top Layer-Tin_M_Top" (solid, pour order 89): 6095.42,4185 6095.42,3845 5675.42,3845 5675.42,4500 5805.42,4500 5805.42,4100 5985.42,4100 5985.42,4185
TOUT_P_TOP on Top Layer "Top Layer- Tout_P_top" (solid, pour order 91): 5084.42,3715 6134.42,3715 6134.42,3530 5265.42,3530 5265.42,3320 5315.42,3270 5504.42,3270 5504.42,2785 5369.42,2785 5369.42,3145 5169.42,3145 5084.42,3230
NetC126_1 on Top Layer "Top Layer-Plus Bot" (solid, pour order 92): 3540.42,2775 3540.42,2990 3624.42,2990 3624.42,3285 4110.42,3285 4110.42,3315 4304.42,3315 4304.42,3130 4159.42,3130 4159.42,3095 4129.42,3095 4129.42,3130 4019.42,3130 4019.42,2855 3665.42,2855 3665.42,2775
NetC135_2 on Top Layer "Top Layer-C135" (solid, pour order 94): 5875.42,4160 5875.42,4405 5949,4405 5949,4160
TOUT_P_BOT on Top Layer "Top Layer- Tout_P_bot" (solid, pour order 95): 3270.42,2775 3270.42,3270 3195.42,3270 3140.42,3325 3140.42,3540 4009.42,3540 4009.42,3725 2959.42,3725 2959.42,3210 3059.42,3110 3135.42,3110 3135.42,2775
TOUT_M_BOT on Top Layer "Top Layer-Tout_M_Bot" (solid, pour order 98): 3435.42,3485 4010.42,3485 4010.42,3300 3805.42,3300 3805.42,3305 3435.42,3305
NetC232_2 on Top Layer "Top Layer-C232_2" (solid, pour order 101): 4025.42,3675 4181.97,3675 4181.97,3575 4229.42,3575 4229.42,3350 4087.09,3350 4087.09,3300 4025.42,3300 4025.42,3430 4101.32,3430 4101.32,3540 4025.42,3540
NetC234_2 on Top Layer "Top Layer-C234" (solid, pour order 103): 6150.42,3670 6275.42,3670 6275.42,3557 6323.42,3557 6323.42,3355 6215.42,3355 6215.42,3290 6150.42,3290 6150.42,3420 6215.42,3420 6215.42,3535 6150.42,3535
TIN_P_BOT on Top Layer "Top Layer-Tin_P_Bot" (solid, pour order 104): 6210.42,4325 6210.42,4530 5395.42,4530 5395.42,4340 5305.42,4340 5305.42,4695 6375.42,4695 6375.42,4540 6620.42,4540 6620.42,4325
TIN_P_BOT on Top Layer "Top Layer-Tin_P_Bot" (solid, pour order 106): 4070.42,4325 4070.42,4525 3265.42,4525 3265.42,4350 3185.42,4350 3185.42,4675 4279.43,4675 4279.49,4539.84 4616.42,4539.84 4616.42,4324.84
GNDF1 on Top Layer "Top Layer-GNDF1" (solid, pour order 116): 4439.42,2915 4439.42,3330 4512.42,3330 4512.42,3485 4474.42,3485 4474.42,3460 4354.42,3460 4354.42,3095 4204.42,3095 4204.42,3060 4329.42,3060 4329.42,2915
TOUT_M_TOP on Top Layer "Top Layer-Tout_M_top" (solid, pour order 117): 5559.42,3470 6134.42,3470 6134.42,3290 5559.42,3290
TIN_M_BOT on Top Layer "Top Layer-Tin_M_Bot" (solid, pour order 97): 3960.42,4180 3959.98,4018 3803,4018 3803,3850 3535.42,3850 3535.42,4510 3665.42,4510 3665.42,4105 3845.42,4105 3845.42,4180
NetQ36_1 on Top Layer "Top Layer-Q36" (solid, pour order 88): 2424,2845 2424,2734 2379.42,2734 2379.42,2577 2508.42,2577 2508.42,2845
BAT0 on Top Layer "Top Layer-USB GND" (solid, pour order 82): 390,4095 510,4095 510,4190 650,4190 650,4295 90,4295 90,4060 180,4060 180,4105 300,4105 300,4060 390,4060
BAT0 on Top Layer "Top Layer-USB GND" (solid, pour order 83): 90,3830 90,3730 510,3730 510,3860 395,3860 395,3895 310,3895 310,3830 300,3830 300,3785 180,3785 180,3830

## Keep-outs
Keep-Out Layer:
  lines w10: 49.43,926.64 ccw(c200,1020) 50.33,1114.79 ; 49.88,5005.92 ccw(c200,5100) 294.08,5250.12 ; 7505.92,5250.12 ccw(c7600,5100) 7750.12,5005.92 ; 7532.14,36.35 cw(c7600,200) 7749.84,294.53 ; 50,36 50,5250 7750,5250 7750,36 1752.57,36 543.47,36 50,36
  lines w290: 500,2223 999.7,2223.21
  lines w314.96: -49.12,2223.21 500,2223 ; 994.62,2227.5 1170,2052.12 1170,1100 1564,706 1564,-66
  text ".Layer_Name" at 13039.5,722.5 h80

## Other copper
Top Layer:
  rectangle net NetC114_2: 1908,3650 1972,3680
  rectangle net BAT0: 6762.42,3574 6860.42,3640
  rectangle net BAT0: 4660.42,3568 4761.42,3634
  rectangle net NetD25_2: 2334.42,2372 2508.42,2438
  rectangle net NetT2_2: 3315.42,4355 3495.42,4510
  rectangle net NetT3_9: 5323.42,3315 5499.42,3469
  rectangle net NetC125_2: 3753.42,4163 3823.42,4406
  rectangle net NetT3_2: 5442.42,4342 5618.42,4496
  rectangle net NetQ14_5: 6221.94,2876.24 6310.42,2942.24
  rectangle net NetQ15_3: 6221.94,2976.24 6310.42,3042.24
  rectangle net NetQ2_3: 4126.42,2975 4213.42,3043
  rectangle net NetQ1_5: 4126.42,2875 4213.42,2943
  rectangle net +12VF1: 2560.42,1948 2727.42,2063
  rectangle net NetC4_1: 7012.42,1251 7077.42,1312
  rectangle net TIN_P_BOT: 1502,1339 1606,1489
  rectangle net NetC135_2: 5877,4161 5949,4401
  rectangle net +12V: 1919,1593 2003,1668
  rectangle net NetT2_9: 3200,3328 3375,3482
  text "C 2011 TI" at 98,2897 h60
  text "880" at 13604.5,877.5 h80
  text ".Layer_Name" at 13042,720 h80
MidLayer2:
  rectangle net GNDF2: 6429.42,2898 6537.42,3195
  rectangle net BAT0: 6619.42,2367 6753.17,2501
  rectangle net NetC125_2: 3823,4257 3934,4409
  rectangle net TIN_M_BOT: 3823,3852 3934,4004
  rectangle net TIN_M_TOP: 5954,3851 6074,4003
  rectangle net NetC135_2: 5964,4258 6075,4410
  rectangle net BAT0: 4549.42,3582 4666.42,3799
  rectangle net BAT0: 6648.84,3588.15 6765.84,3805.15
  rectangle net BAT0: 4950.42,2807.24 5084.17,2941.24
  rectangle net TIN_P_BOT: 5740.42,1400 6155.42,1595
MidLayer3:
  rectangle net BAT0: 6619.42,2367 6753.17,2501
  rectangle net NetC125_2: 3823,4257 3934,4409
  rectangle net TIN_M_BOT: 3823,3852 3934,4004
  rectangle net TIN_M_TOP: 5950,3851 6076,4003
  rectangle net NetC135_2: 5964,4258 6075,4410
  rectangle net BAT0: 4549.42,3582 4666.42,3799
  rectangle net BAT0: 6648.84,3588.15 6765.84,3805.15
  rectangle net BAT0: 4950.42,2807.24 5084.17,2941.24
  rectangle net GNDF1: 4337,2926 4437,3051
  rectangle net GNDF2: 6425,2913 6541,3137
MidLayer4:
  rectangle net TIN_M_BOT: 3815,3851 3941.29,4003
  rectangle net TIN_M_TOP: 5954,3848 6072,4005
  rectangle net NetC125_2: 3823,4257 3934,4409
  rectangle net NetC135_2: 5964,4258 6075,4410
  pour cut-out: 7346.42,2140 7495.42,2140 7495.42,1756.13 7497.94,1753.61 7619.62,1753.61 7619.62,1475.8 7620.42,1475 7618.58,1473.16 7495.42,1473.16 7495.42,1397.15 7497.57,1395 7605.42,1395 7605.42,1260 7338,1260 7338,1165 7590.42,1165 7590.42,980 7495,980 7495.42,410 7495,130 5431.19,129.33 5431.19,743.93 5550,745 5550,310 7005,310 7005.42,990 6910.42,990 6910.42,1070 7005.42,1070 7005.42,1321 6650.42,1321 6650.42,1460 6795.42,1460 6795.42,1390 6875.42,1390 6875.42,1430 7025.42,1430 7025.42,1750 7346.42,1750
MidLayer1:
  rectangle net NetC125_2: 3823,4257 3934,4409
  rectangle net TIN_M_BOT: 3823,3852 3934,4004
  rectangle net TIN_M_TOP: 5957,3851 6068,4003
  rectangle net NetC135_2: 5964,4258 6075,4410
Bottom Layer:
  rectangle net TIN_M_BOT: 3824,3852 3935,4004
  rectangle net BAT0: 5125,4199 5422,4504
  rectangle net BAT0: 4953.42,2809 5084.42,2943
  rectangle net BAT0: 6648.42,3589 6765.42,3806
  rectangle net BAT0: 4549.42,3582 4666.42,3799
  rectangle net BAT0: 6619.42,2367 6753.17,2501
  rectangle net NetC125_2: 3823,4257 3934,4409
  rectangle net TIN_M_TOP: 5950,3851 6075,4003
  rectangle net NetC135_2: 5964,4258 6075,4410
  rectangle net +12V: 5208,4588 5298,4714
  text "551600748-001 RevA" at 3699,3709 h60
  text "880" at 13604.5,877.5 h80
  text ".Layer_Name" at 13039.5,722.5 h80
  text "UL94V-0" at 4330.42,70 h60
  text "MADE IN U.S." at 3773,65 h60

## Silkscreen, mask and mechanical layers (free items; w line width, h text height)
Top Overlay:
  lines w10: 1778,3197 1789,3208 1957,3208 2061,3104 2061,2961 ; 1988,3181 1988,3310 2061,3383 ; 4176,3485 4169,3492 4169,3772 4231,3834 4231,3932 ; 4231,4008 4231,4024 4246,4039 4399,4039 4435,4003 ; 4293,3484 4366,3484 4388,3506 4388,3761 4435,3808 4435,4003 ; 4564,4056 4488,4056 4435,4003 ; 6276,3494 6276,3620 6330,3674 6330,3815 ; 6340,4055 6340,4065 6349,4074 6401,4074 6448,4027 6448,3890 6467,3871 6532,3871 6542,3861 6542,3549 6473,3480 6392,3480 ; 6427,4049 6442,4064 6472,4064 ; 6548.98,4213.33 6548.98,4171.98 6472,4095 6472,3897 6484,3885 6624.84,3885 6651.59,3911.75 6680.75,3911.75 6740,3971 6740,4048 6769,4077 6769,4152 6776,4159 6801,4159 6820,4178 6820,4213 6788,4245 6661,4245 6626,4280 6626,4662 6605,4683 6562,4683 6545,4666 6545,4392 6553,4384 ; 2061,3383 2006,3438 2006,3749 2056,3799 2272,3799 2409,3662 2409,3501 2291,3383 2061,3383 ; 4564,3939 4564,4160 4630,4226 4630,4695 4665,4730 4761,4730 4908,4583 4908,4035 4781,3908 4595,3908 4564,3939
  text "EM1401 RevA2" at 82,3303 h80
  text "GND" at 373,1610 h40
  text "+5V" at 371,1514 h40
  text "GND" at 374,1412 h40
  text "880" at 11484.5,1222.5 h40
  text ".Layer_Name" at 11494.5,1002.5 h40
  text "+" at 2096,687 h100
Bottom Overlay:
  region: 3001.42,3686 3001.42,3561 2661.42,3561 2661.42,3686
  lines w7: 421.79,2203 1036.79,2203 ccw(c1036.79,2234) 1036.79,2265 421.79,2265 ; 461.79,2203 cw(c461.79,2234) 461.79,2265
  lines w10: 2960.42,1405 2960.42,1480 2894.42,1546 2894.42,1567 2857.56,1603.85 2234.27,1603.85 2210.42,1580 2210.42,1365 2222.92,1352.5 2740.42,1352.5 2803.92,1289 2924.42,1289 2960.42,1325 2960.42,1400 3270.42,1400 3445.42,1575 4555.42,1575 4590.42,1610 4590.42,1967.58 4562,1996 3666.42,1996 3625.42,1955 3625.42,1605 3655.42,1575 ; 6169,1544 6133,1508 5893,1508 5864,1537 5764,1637 5764,1699 5764,1798 5826,1860 6155,1860 6188,1827 6188,1681 ; 6389,1482 6352,1445 6352,1406 6323,1377 6293,1377 6286,1370 6202,1370 6169,1403 6169,1570 6169,1661 6236,1728 6351,1728 6508,1728 6536,1700 6536,1578 6505,1547 6505,1491 6498.5,1484.5 ; 6458,1181 6458,1111 6494,1075 6505,1075 ; 6510,1242 6642,1242 6646.5,1237.5 ; 6556.5,1050.5 6583.05,1023.95 6583.05,983.59 ; 6582.91,941.27 6582.91,890.09 6597,876 6693,876 6721,904 ; 6622,1940 6642.42,1919.58 6642.42,1651.58 6665,1629 6800,1629 6866,1695 6866,1909 6805,1970 6652.42,1970 6622.42,1940 6622.42,2331.58 6611,2343 6368,2343 6328,2303 6328,1907 6349,1886 6477,1886 6506,1857 6614.42,1857 6642.42,1885 ; 6658.09,1227.22 6664,1221.31 6664,1184 ; 6712.85,1112.15 6753,1072 6753,936 ; 6885,663 6885,675 6860,700 6827,700 6721,806 6721,904 ; 6886,573 6911,548 7009,548 7046,585 7046,930 7040,936 6753,936 ; 7159.42,1125 7155.42,1121 6883,1121 6870,1134 6870,1229 6883,1242 7214,1242 7227,1229 ; 7226,1138 7213,1125 7152.04,1125 7281.42,995.62 7281.42,850.42 7281.42,719.08 7307.5,693 7700,693 7759,752 7759,938 7740,957 7317,957 7281,921 ; 7227.42,1169 7227.42,1230 ; 6721,904 6753,936
  text "980600748 -" at 3716.42,3591 h60
  text "880" at 11484.5,1222.5 h40
  text ".Layer_Name" at 11494.5,1002.5 h40
Top Paste:
  text "881" at 11484.5,1222.5 h80
  text ".Layer_Name" at 11494.5,1002.5 h80
Bottom Paste:
  text "881" at 11484.5,1222.5 h80
  text ".Layer_Name" at 11494.5,1002.5 h80
Top Solder:
  text "880" at 11484.5,1222.5 h80
  text ".Layer_Name" at 11489.5,1002.5 h80
  text ".Layer_Name" at 11494.5,1002.5 h80
Bottom Solder:
  text "880" at 11484.5,1222.5 h80
  text ".Layer_Name" at 11489.5,1002.5 h80
Drill Guide:
  text ".Layer_Name" at 11494.5,1002.5 h80
M1 Board Outline:
  the board outline again, w7
M2 Board Dimensions:
  rectangle: 124.5,-410.5 499.5,-285.5
  rectangle: -0.5,-285.5 124.5,-160.5
  lines w7: -0.5,-285.5 999.5,-285.5 ; 124.5,-410.5 124.5,-160.5 ; 249.5,-410.5 249.5,-160.5 ; 421.63,2203 1036.63,2203 ccw(c1036.63,2234) 1036.63,2265 421.63,2265 ; 461.63,2203 cw(c461.63,2234) 461.63,2265 ; 499.5,-410.5 499.5,-160.5 ; 749.5,-410.5 749.5,-160.5 ; -0.5,-410.5 -0.5,-160.5 999.5,-160.5 999.5,-410.5 -0.5,-410.5
  lines w10: -0.5,-475.5 -0.5,-455.5 ; 59.5,-485.5 -0.5,-465.5 ; 59.5,-445.5 -0.5,-465.5 ; 223.58,-465.5 -0.5,-465.5 ; 775.42,-465.5 999.5,-465.5 ; 939.5,-485.5 999.5,-465.5 ; 939.5,-445.5 999.5,-465.5 ; 999.5,-475.5 999.5,-455.5 ; 200,200 200,5100 7600,5100 7600,200 200,200
  text "Slot cut through pcb" at 295,2435 h60
  text "1000 (mil)" at 233.58,-501.49 h60
M3 3D STEP Top:
  text ".Layer_Name" at 11494.5,1002.5 h80
M4 3D STEP Bottom:
  text ".Layer_Name" at 11494.5,1002.5 h80
M5 Assembly Top:
  text ".Layer_Name" at 11494.5,1002.5 h80
  text "COMPONENTS MARKED 'DNP' SHOULD NOT BE POPULATED, AND MAY NOT BE IN BILL OF MATERIALS" at 1473.5,-318.5 h60
M6 Assembly Bottom:
  text ".Layer_Name" at 11494.5,1002.5 h80
  text "COMPONENTS MARKED 'DNP' SHOULD NOT BE POPULATED, AND MAY NOT BE IN BILL OF MATERIALS" at 1473.5,-318.5 h60
M9 Title Sheet:
  lines w5: -491.5,1341.5 -291.5,1341.5 ; -491.5,3716.5 -291.5,3716.5 ; -291.5,-522.5 9803.5,-523.5 14303.5,-523.5 ; 2008.5,-1033.5 2008.5,-833.5 ; 4362.5,8266.5 4362.5,8466.5 ; 4508.5,-1033.5 4508.5,-833.5 ; 7008.5,-1033.5 7008.5,-833.5 ; 7008.5,8266.5 7008.5,8466.5 ; 8803.5,-823.5 8803.5,-223.5 14303.5,-223.5 ; 9508.5,-1033.5 9508.5,-833.5 ; 9508.5,8266.5 9508.5,8466.5 ; 10615.5,-523.5 10615.5,-223.5 ; 11303.5,-833.5 11303.5,-223.5 11303.5,376.5 14303.5,376.5 ; 11303.5,76.5 14303.5,76.5 ; 12008.5,-1033.5 12008.5,-833.5 ; 12008.5,8266.5 12008.5,8466.5 ; 12628.5,-823.5 12628.5,-223.5 ; 14304.5,3799.5 14504.5,3799.5 ; 14308.5,366.5 14308.5,-833.5 ; 14308.5,1341.5 14508.5,1341.5 ; 14308.5,6091.5 14508.5,6091.5 ; 14308.5,-833.5 -291.5,-833.5 -291.5,8266.5 14308.5,8266.5 14308.5,-833.5 ; -491.5,-1033.5 14508.5,-1033.5 14508.5,8466.5 -491.5,8466.5 -491.5,-1033.5
  text "1" at 739.84,8336.5 h70
  text "2" at 3089.5,8336.5 h70
  text "3" at 5578.84,8336.5 h70
  text "4" at 8231.51,8336.5 h70
  text "5" at 10730.5,8336.5 h70
  text "6" at 13235.5,8336.5 h70
  text "A" at -416.5,7193.5 h70
  text "A" at 14385,7183 h70
  text "B" at 14379.5,4896.5 h70
  text "B" at -416.5,4813.5 h70
  text "C" at 14379.5,2521.5 h70
  text "C" at -416.5,2438.5 h70
  text ".Layer_Name" at 11494.5,1002.5 h80
  text "PROJECT TITLE:" at 11343.5,276.5 h45
  text ".PRJ_Title" at 11393.5,156.5 h70
  text "D" at -416.5,68.5 h70
  text "D" at 14383.5,68.5 h70
  text "DESIGNED FOR:" at 11343.5,-13.5 h45
  text ".PRJ_Customer" at 11393.5,-168.5 h70
  text "REV:" at 8853.5,-323.5 h45
  text "PRINT DATE:" at 10691.5,-323.5 h45
  text "PADC NUMBER:" at 11343.5,-323.5 h45
  text "FAB DRAWING NUMBER:" at 12888.5,-323.5 h45
  text ".PCB_MinorRev" at 8878.5,-463.49 h70
  text ".PRJ_PADC" at 11393.5,-463.49 h70
  text "551" at 12938.5,-463.49 h70
  text ".PRJ_BasePN" at 13133.5,-463.49 h70
  text ".Print_Date" at 10693.5,-465.16 h70
  text "National Semiconductor and/or its licensors do not warrant the accuracy or completeness of this specification or any information contained therein. National and/or its licensors do not warrant that" at -186.5,-607.34 h45
  text "FILE NAME:" at 8853.5,-623.5 h45
  text "ALTIUM DESIGNER VERSION:" at 12888.5,-623.5 h45
  text "this design will meet the specifications, will be suitable for your application or fit for any particular purpose, or will operate in an implementation. National and/or its licensors do not warrant" at -186.5,-710.67 h45
  text ".print_Scale" at 11393.5,-725.5 h70
  text ".Pcb_File_Name_No_Path" at 8878.5,-756.83 h70
  text ".Application_BuildNumber" at 12938.5,-790.15 h70
  text "that the design is production worthy. You should completely validate and test your design implementation to confirm the system functionality for your application." at -186.5,-814 h45
  text "1" at 739.84,-963.5 h70
  text "2" at 3235.5,-963.5 h70
  text "3" at 5724.84,-963.5 h70
  text "4" at 8231.51,-963.5 h70
  text "5" at 10730.5,-963.5 h70
  text "6" at 13235.5,-963.5 h70
M10 Fab Notes:
  drawing of 203 lines, arcs and shapes, not listed
  text "DESIGN INFORMATION" at 12366.02,8109 h60
  text "(REFER ALSO ARRAY/PANEL PROFILING INFORMATION)" at 12004.46,7947.29 h60
  text "BOARD SIZE" at 11318.46,7943 h60
  text "5300MIL" at 11780.78,7815.18 h60
  text "X" at 12286.46,7815.18 h60
  text "7800MIL" at 12517.78,7815.18 h60
  text "Number of Layers :" at 11721.46,7618 h60
  text "6" at 12816.27,7608 h60
  text "MIN. TRACK WIDTH:" at 11721.46,7479 h60
  text "8" at 12817.7,7479 h60
  text "MIL" at 12972.46,7479 h60
  text "MIN. CLEARANCE:" at 11721.46,7347 h60
  text "8" at 12817.7,7347 h60
  text "MIL" at 12972.46,7347 h60
  text "MIN. VIA PAD SIZE:" at 11721.46,7215 h60
  text "24" at 12787.71,7215 h60
  text "MIL" at 12972.46,7215 h60
  text "0.05mm (2MIL)" at 12416.46,7073.29 h60
  text "MINIMUM ANNULAR RING" at 11392.23,7069 h60
  text "EXTERNAL" at 13124.46,7069 h60
  text "PER" at 11592.23,6951 h60
  text "IPC-D-275 CLASS 2 LEVEL C" at 11812.23,6951 h60
  text "MIL, HOLES" at 13300.46,6838.71 h60
  text "+/-" at 12908,6838 h60
  text "+/-" at 13762,6838 h60
  text "REGISTRATION TOLERANCES:" at 11392.23,6833 h60
  text "METAL" at 12592,6833 h60
  text "5" at 13168.2,6833 h60
  text "3" at 14001.2,6833 h60
  text "MIL" at 14117.46,6833 h60
  text "MATERIAL:" at 11317.46,6623.54 h60
  text "FR-4 High Tg" at 12303.9,6483.21 h60
  text "FR-4" at 11778.46,6474.64 h60
  text "X" at 12150.46,6474.64 h60
  text "OTHER" at 13226.46,6474.64 h60
  text "62 MIL (1.6mm) +/-10%" at 12058.56,6311.92 h60
  text "THICKNESS:" at 11392.23,6307.64 h60
  text "X" at 11930.4,6307.64 h60
  text "OTHER" at 13343.46,6307.64 h60
  text "TOLERANCE:" at 11392.23,6149.64 h60
  text "X" at 12231.53,6149.64 h60
  text "ANSI IPC-6012 TYPE 3 CLASS 2" at 12418.48,6149.64 h60
  text "OTHER +/-" at 12418.46,5993.64 h60
  text "BOW & TWIST:" at 11392.23,5836.64 h60
  text "X" at 12231.53,5836.64 h60
  text "ANSI IPC-6012 TYPE 3 CLASS 2" at 12418.48,5836.64 h60
  text "OTHER +/-" at 12418.46,5678.13 h60
  text "COPPER THICKNESS (FINISHED):" at 11317.46,5542.64 h60
  text "1.4MIL (1oz)" at 12197.46,5389.92 h60
  text "2MIL (1.4oz)" at 12964.46,5389.92 h60
  text "X" at 13569,5390 h60
  text "2.8MIL (2oz)" at 13691.46,5389.92 h60
  text "OUTER:" at 11674.46,5385.64 h60
  text "1.4MIL (1oz)" at 12547.46,5232.92 h60
  text "2.8MIL (2oz)" at 13391.46,5232.92 h60
  text "INNER SIGNAL:" at 11674.46,5228.64 h60
  text "X" at 13256,5226 h60
  text "DRILLING:" at 11317.46,5089.64 h60
  text "REFERENCE:" at 11392.23,4972.64 h60
  text "X" at 12040.46,4972.64 h60
  text "AS SHOWN" at 12227.46,4972.64 h60
  text "X" at 12941.46,4972.64 h60
  text "NC_DRILL FILES" at 13078.46,4972.64 h60
  text "PTH MIN COPPER THICKNESS:" at 11392.23,4814.64 h60
  text "X" at 12742.46,4814.64 h60
  text "1MIL" at 12879.46,4814.64 h60
  text "OTHER" at 13376.46,4814.64 h60
  text "BOARD FINISH:" at 11317.46,4655.64 h60
  text "SILKSCREEN:" at 11472.68,4537.64 h60
  text "X" at 12421.46,4537.64 h60
  text "TOP" at 12547.46,4537.64 h60
  text "X" at 12931.46,4537.64 h60
  text "BOTTOM" at 13058.46,4537.64 h60
  text "SILKSCREEN COLOR:" at 11472.68,4370.64 h60
  text "X" at 12420.42,4370.64 h60
  text "WHITE" at 12547.46,4370.64 h60
  text "OTHER" at 13058.46,4370.64 h60
  text "SOLDER RESIST COLOR:" at 11472.68,4200.64 h60
  text "X" at 12040.42,4041.44 h60
  text "GREEN" at 12167.46,4041.44 h60
  text "BLUE" at 12758.46,4041.44 h60
  text "OTHER" at 13296.46,4041.44 h60
  text "IMMERSION GOLD (ENIG)" at 12378.46,3852.92 h60
  text "SURFACE FINISH:" at 11317.46,3848.64 h60
  text "X" at 12191.51,3848.64 h60
  text "Pb-FREE HASL" at 13610.75,3848.64 h60
  text "OTHER" at 12378.46,3691.64 h60
  text "ARRAY/PANEL:" at 11317.46,3512.64 h60
  text "CUT AND TRIM PER MECH LAYER 1" at 12378.46,3508.35 h60
  text "N.C. ROUTE" at 12378.46,3356.64 h60
  text "X" at 13057.46,3356.64 h60
  text "V. SCORE" at 13244.46,3356.64 h60
  text "CERTIFICATION:" at 11317.46,3219.64 h60
  text "MATERIALS AND WORKMANSHIP FOR ALL PCBS" at 12042.46,3219.64 h60
  text "TO MEET OR EXCEED THE REQUIREMENTS OF:" at 12042.46,3121.64 h60
  text "X" at 11668.96,2985.13 h60
  text "ANSI IPC-A-600F CLASS ->" at 11807.96,2985.13 h60
  text "X" at 13447.02,2985.13 h60
  text "2" at 13565.96,2985.14 h60
  text "1" at 13250.96,2983.64 h60
  text "3" at 13919.96,2983.64 h60
  text "X" at 11671.02,2825.64 h60
  text "UL 94V-0" at 11807.96,2825.64 h60
  text "X" at 12483.02,2825.64 h60
  text "RoHS" at 12619.96,2825.64 h60
  text "OTHER" at 13264.36,2825.64 h60
  text "PER ORDER" at 13661.42,2825.64 h60
  text "ADDITIONAL REQUIREMENTS:" at 11317.46,2684.64 h60
  text "MICROSECTION:" at 11392.23,2569.64 h60
  text "YES" at 12297.96,2569.64 h60
  text "REQUIRED" at 13159.46,2413.49 h60
  text "BARE BOARD ELEC. TEST:" at 11392.23,2410.64 h60
  text "NONE" at 12697.96,2410.64 h60
  text "X" at 13032.46,2410.64 h60
  text "PER ORDER" at 13751.46,2410.64 h60
  text "MANUFACTURER'S ID/LOGO:" at 11392.23,2253.64 h60
  text "RAIL" at 12857.96,2249.35 h60
  text "X" at 13232.46,2249.35 h60
  text "METAL" at 13349.77,2249.35 h60
  text "SILK" at 13861.46,2249.35 h60
  text ".Layer_Name" at 562,440.51 h60
  text "880" at 3102.5,440.51 h60
M11 Gerber Information:
  drawing of 35 lines, arcs and shapes, not listed
  text "ALL ARTWORK VIEWED FROM TOP SIDE" at 11099.5,1669.68 h80
  text "BOARD NAME" at 10353,1445.83 h80
  text ".PRJ_Title" at 11479.5,1445.83 h80
  text "ARTWORK #" at 10358,1222.5 h80
  text ".prj_BasePN" at 11729.5,1222.5 h80
  text ".pcb_minorRev" at 12284.5,1222.5 h80
  text "LAYER NAME" at 10368,1002.5 h80
  text ".plot_File_Name" at 11484.5,809.66 h80
  text "PLOT NAME" at 10358,783 h80
  text "PRINT DATE" at 10358,563 h80
  text ".Print_Date" at 11484.5,563 h80
  text ".Print_Time" at 12319.5,563 h80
